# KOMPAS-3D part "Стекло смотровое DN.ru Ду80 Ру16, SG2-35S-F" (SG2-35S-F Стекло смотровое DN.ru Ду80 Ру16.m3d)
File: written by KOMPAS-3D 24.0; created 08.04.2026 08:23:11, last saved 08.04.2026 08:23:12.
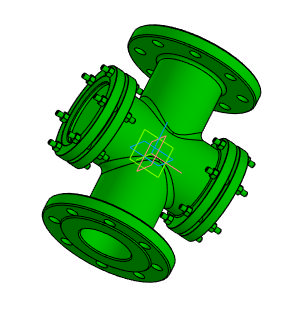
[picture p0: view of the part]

Document properties: Автор: Main; Полное имя файла: D:\DN.ru Аутсерс\Стекло смотровое DN.ru\SG2-35S-F Стекло смотровое DN.ru Ду80 Ру16\SG2-35S-F Стекло смотровое DN.ru Ду80 Ру16.m3d

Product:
- Body: Тело 1  | qty 1
    Масса: 19.954238
- Part/product: Стекло смотровое DN.ru Ду80 Ру16  | designation SG2-35S-F
    Масса: 20.5
    Раздел спецификации: Прочие изделия
    Примечание: D500-00098

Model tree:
1. Операция без истории:1

Expressions: SG2-35S-F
